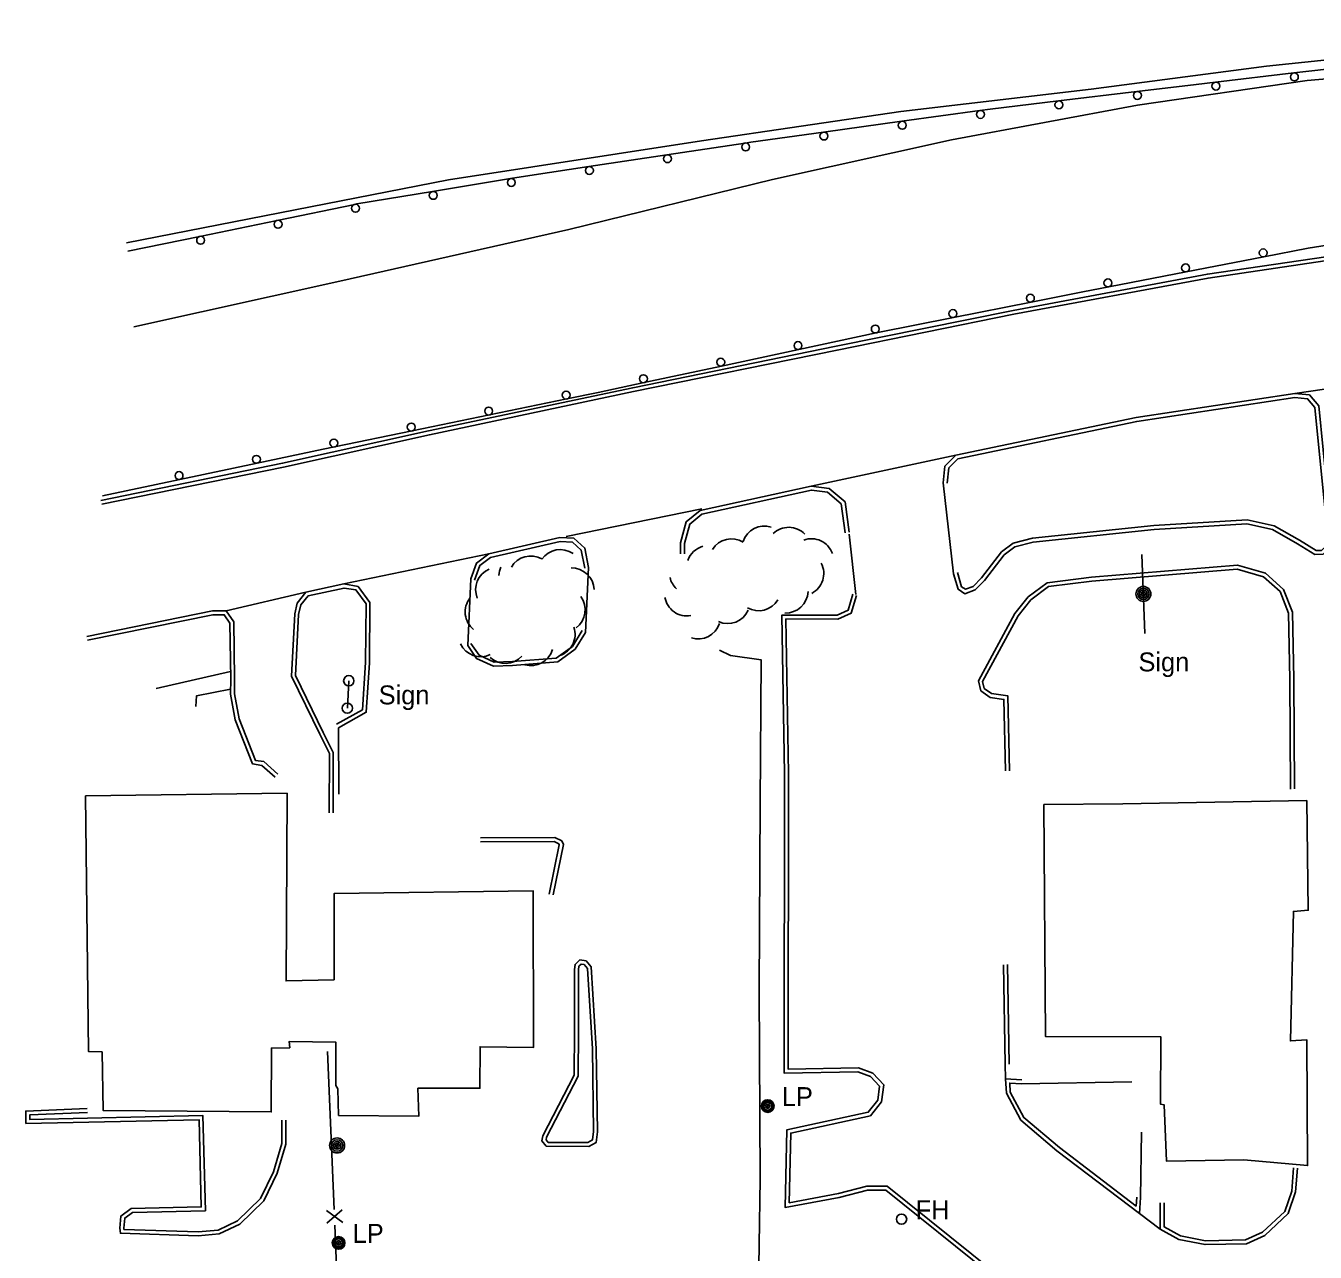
# Model space of a CAD drawing. Extents: x 2402803 to 2427059, y 6985292 to 6997652.
# Drawn here: x 2403480.7 to 2403806.8, y 6991498.2 to 6991808.6 of the extents above; entities that cross this region are included whole.
import ezdxf

# ---------------------------------------------------------------- set-up
doc = ezdxf.new("R2010")
doc.units = 0
for name, color, linetype in [('p_drainage riprap', 7, 'Continuous'), ('p_dtm sidewalk', 7, 'Continuous'), ('p_road - paved curb', 7, 'Continuous'), ('p_road guard rails', 7, 'Continuous'), ('p_structure building', 7, 'Continuous'), ('p_structure fence', 7, 'Continuous'), ('p_structure sign', 7, 'Continuous'), ('p_utility manhole', 7, 'Continuous'), ('p_veg woods', 7, 'Continuous')]:
    doc.layers.add(name, color=color, linetype=linetype)

msp = doc.modelspace()

# ---------------------------------------------------------------- linework, layer by layer
at = {"layer": 'p_drainage riprap'}
msp.add_lwpolyline([(2403508.03, 6991732.43), (2403560.09, 6991744.02), (2403618.02, 6991757.07), (2403669.54, 6991769.69), (2403714.85, 6991779.71), (2403761.84, 6991788.48), (2403804.73, 6991794.78), (2403857.86, 6991799.33), (2403912.85, 6991802.26), (2403942.46, 6991802.6)], dxfattribs=at)
at = {"layer": 'p_dtm sidewalk'}
for points in [[(2403532.49, 6991645.19), (2403513.69, 6991640.88)], [(2403532.5, 6991640.76), (2403523.85, 6991639.01), (2403523.66, 6991636.37)], [(2403732.55, 6991540.86), (2403760.45, 6991541.37)], [(2403762.86, 6991528.63), (2403762.65, 6991512.09)]]:
    msp.add_lwpolyline(points, dxfattribs=at)
at = {"layer": 'p_road - paved curb'}
for points in [[(2403941.62, 6991808.61), (2403890.54, 6991806.45), (2403844.59, 6991803.59), (2403794.47, 6991798.4), (2403750.1, 6991792.54), (2403702.03, 6991786.92), (2403651.62, 6991779.47), (2403587.61, 6991769.62), (2403506.12, 6991753.65)], [(2403499.71, 6991688.52), (2403545.62, 6991697.9), (2403582.56, 6991706.1), (2403634.2, 6991717.03), (2403685.67, 6991727.52), (2403730.43, 6991736.57), (2403779.53, 6991745.76), (2403819.86, 6991751.68), (2403867.19, 6991757.46), (2403897.69, 6991759.96), (2403942.34, 6991762.94)], [(2403499.91, 6991687.54), (2403545.83, 6991696.92), (2403582.77, 6991705.12), (2403634.4, 6991716.05), (2403685.87, 6991726.54), (2403730.62, 6991735.59), (2403779.69, 6991744.77), (2403819.99, 6991750.69), (2403867.29, 6991756.46), (2403897.76, 6991758.96), (2403942.41, 6991761.94)], [(2403801.64, 6991715.52), (2403837.37, 6991720.76)], [(2403715.36, 6991669.96), (2403716.52, 6991666.01), (2403718.2, 6991664.9), (2403720.83, 6991665.83), (2403723.17, 6991668.25), (2403728.16, 6991674.74), (2403730.86, 6991676.76), (2403735.45, 6991677.94), (2403766.03, 6991681.11), (2403789.48, 6991682.61), (2403796.01, 6991681.1), (2403802.32, 6991677.55), (2403806.73, 6991674.79), (2403808.81, 6991674.87), (2403810.81, 6991676.72), (2403811.03, 6991679.01), (2403807.7, 6991712.44), (2403805.34, 6991715.19), (2403801.64, 6991715.52), (2403761.48, 6991709.45), (2403715.93, 6991699.91), (2403713.16, 6991697.17), (2403712.69, 6991692.97)], [(2403716.32, 6991670.24), (2403717.38, 6991666.64), (2403718.34, 6991666.01), (2403720.27, 6991666.69), (2403722.41, 6991668.9), (2403727.45, 6991675.46), (2403730.42, 6991677.68), (2403735.27, 6991678.93), (2403765.95, 6991682.11), (2403789.56, 6991683.62), (2403796.38, 6991682.04), (2403802.83, 6991678.41), (2403807, 6991675.8), (2403808.4, 6991675.86), (2403809.85, 6991677.2), (2403810.03, 6991679.01), (2403806.74, 6991712.03), (2403804.85, 6991714.23), (2403801.67, 6991714.51), (2403761.66, 6991708.47), (2403716.42, 6991698.99), (2403714.11, 6991696.71), (2403713.68, 6991692.86)], [(2403679.34, 6991692.13), (2403715.93, 6991699.91)], [(2403688.89, 6991680.45), (2403687.88, 6991688.13), (2403683.86, 6991691.55), (2403679.34, 6991692.13), (2403651.26, 6991685.92), (2403647.72, 6991683.1), (2403646.25, 6991677.74), (2403646.28, 6991674.95)], [(2403687.9, 6991680.32), (2403686.94, 6991687.62), (2403683.44, 6991690.6), (2403679.39, 6991691.12), (2403651.7, 6991684.99), (2403648.6, 6991682.52), (2403647.25, 6991677.61), (2403647.28, 6991674.96)], [(2403712.69, 6991692.97), (2403715.36, 6991669.96)], [(2403617.39, 6991679.41), (2403651.65, 6991686.36)], [(2403623.04, 6991671.53), (2403622.11, 6991676.45), (2403619.32, 6991678.92), (2403615.72, 6991679.1), (2403597.79, 6991674.99), (2403594.7, 6991672.65), (2403593.21, 6991668.63)], [(2403622.06, 6991671.34), (2403621.19, 6991675.93), (2403618.92, 6991677.94), (2403615.81, 6991678.09), (2403598.22, 6991674.06), (2403595.54, 6991672.03), (2403594.15, 6991668.28)], [(2403690.64, 6991664.68), (2403688.89, 6991679.92)], [(2403561.16, 6991667.37), (2403597.79, 6991674.99)], [(2403622.24, 6991655.06), (2403623.04, 6991671.53)], [(2403801.53, 6991615.48), (2403801.37, 6991643.25), (2403801.05, 6991660.19), (2403798.76, 6991665.99), (2403794.22, 6991670.1), (2403787.13, 6991672.11), (2403750.24, 6991669.04), (2403738.98, 6991667.66), (2403734.2, 6991664.07), (2403730.8, 6991659.87), (2403721.6, 6991642.83), (2403722.19, 6991640.34), (2403724.57, 6991638.66), (2403728.09, 6991638.16), (2403728.45, 6991620.05)], [(2403593.21, 6991668.63), (2403592.45, 6991651.77)], [(2403800.53, 6991615.47), (2403800.37, 6991643.24), (2403800.05, 6991659.99), (2403797.92, 6991665.41), (2403793.72, 6991669.2), (2403787.03, 6991671.1), (2403750.34, 6991668.05), (2403739.37, 6991666.7), (2403734.9, 6991663.34), (2403731.64, 6991659.31), (2403722.66, 6991642.69), (2403723.08, 6991640.94), (2403724.95, 6991639.62), (2403729.07, 6991639.03), (2403729.45, 6991620.07)], [(2403531.4, 6991660.55), (2403551.55, 6991665.24)], [(2403559.78, 6991630.98), (2403566.79, 6991634.9), (2403567.6, 6991647.44), (2403567.74, 6991662.68), (2403564.73, 6991666.75), (2403561.16, 6991667.35), (2403551.55, 6991665.24), (2403549.29, 6991662.5), (2403548.7, 6991659.79), (2403547.89, 6991643.99), (2403555.03, 6991629.36), (2403557.47, 6991624.47), (2403557.4, 6991609.41)], [(2403559.29, 6991631.85), (2403565.83, 6991635.51), (2403566.6, 6991647.48), (2403566.74, 6991662.35), (2403564.17, 6991665.83), (2403561.19, 6991666.33), (2403552.1, 6991664.34), (2403550.22, 6991662.05), (2403549.69, 6991659.66), (2403548.9, 6991644.2), (2403555.93, 6991629.8), (2403558.47, 6991624.7), (2403558.4, 6991609.41)], [(2403745.15, 6991461.32), (2403733.78, 6991484.34), (2403730.03, 6991488.75), (2403724.46, 6991492.84), (2403698.18, 6991513.95), (2403693.56, 6991513.93), (2403686.42, 6991512.13), (2403672.73, 6991509.57), (2403673.17, 6991529.23), (2403693.76, 6991533.69), (2403696.18, 6991536.72), (2403696.64, 6991540.25), (2403694.35, 6991542.71), (2403691.12, 6991543.89), (2403672.49, 6991543.59), (2403672.57, 6991619.4), (2403671.91, 6991659.5), (2403685.88, 6991659.47), (2403688.64, 6991660.72), (2403689.84, 6991664.75)], [(2403746.05, 6991461.76), (2403734.62, 6991484.89), (2403730.72, 6991489.49), (2403725.07, 6991493.63), (2403698.53, 6991514.95), (2403693.43, 6991514.93), (2403686.21, 6991513.11), (2403673.76, 6991510.78), (2403674.15, 6991528.42), (2403694.32, 6991532.79), (2403697.14, 6991536.31), (2403697.69, 6991540.59), (2403694.92, 6991543.57), (2403691.29, 6991544.89), (2403673.49, 6991544.61), (2403673.57, 6991619.41), (2403672.93, 6991658.5), (2403686.1, 6991658.47), (2403689.47, 6991660), (2403690.8, 6991664.46)], [(2403544.46, 6991619.21), (2403540.87, 6991622.39), (2403538.76, 6991622.72), (2403534.62, 6991633.21), (2403533.49, 6991639.53), (2403533.51, 6991643.39), (2403533.32, 6991657.75), (2403531.4, 6991660.55), (2403527.87, 6991660.54), (2403496.12, 6991654.09)], [(2403543.8, 6991618.46), (2403540.43, 6991621.45), (2403538.04, 6991621.82), (2403533.65, 6991632.94), (2403532.49, 6991639.44), (2403532.51, 6991643.39), (2403532.32, 6991657.43), (2403530.87, 6991659.55), (2403527.97, 6991659.54), (2403496.32, 6991653.11)], [(2403592.45, 6991651.77), (2403594.66, 6991648.52), (2403598.94, 6991646.57), (2403603.81, 6991646.72), (2403615.21, 6991647.65), (2403619.67, 6991650.86), (2403622.24, 6991655.06)], [(2403593.28, 6991652.33), (2403595.33, 6991649.31), (2403599.14, 6991647.58), (2403603.75, 6991647.72), (2403614.85, 6991648.62), (2403618.92, 6991651.55), (2403621.39, 6991655.58)], [(2403674.78, 6991469.39), (2403674.72, 6991483.7), (2403665.92, 6991483.64), (2403666.4, 6991516.73), (2403666.15, 6991564.58), (2403666.42, 6991611.88), (2403666.66, 6991648.16), (2403658.88, 6991649.28), (2403656.13, 6991650.61)], [(2403559.86, 6991614.17), (2403559.78, 6991630.98)], [(2403614.07, 6991588.69), (2403616.65, 6991601.42), (2403616.24, 6991602.37), (2403614.52, 6991603.2), (2403595.73, 6991603.12)], [(2403613.09, 6991588.89), (2403615.61, 6991601.31), (2403615.47, 6991601.63), (2403614.29, 6991602.2), (2403595.73, 6991602.12)], [(2403624.98, 6991549.76), (2403623.7, 6991570.46), (2403622.41, 6991572.01), (2403620.78, 6991572.23), (2403619.6, 6991571.08), (2403619.48, 6991569.78), (2403619.49, 6991554.2)], [(2403623.98, 6991549.7), (2403622.72, 6991570.07), (2403621.89, 6991571.07), (2403621.13, 6991571.17), (2403620.56, 6991570.62), (2403620.48, 6991569.73), (2403620.49, 6991554.2)], [(2403727.96, 6991571), (2403728.36, 6991545.84)], [(2403728.96, 6991571.02), (2403729.36, 6991545.86)], [(2403619.49, 6991554.2), (2403619.38, 6991543.05), (2403611.44, 6991527.7), (2403611.18, 6991526.44), (2403612.34, 6991525.05), (2403623.1, 6991525.04), (2403624.93, 6991526.01), (2403625.29, 6991528.71), (2403624.98, 6991549.76)], [(2403620.49, 6991554.19), (2403620.38, 6991542.8), (2403612.39, 6991527.36), (2403612.26, 6991526.71), (2403612.81, 6991526.05), (2403622.85, 6991526.04), (2403624.01, 6991526.65), (2403624.29, 6991528.77), (2403623.98, 6991549.75)], [(2403728.36, 6991545.84), (2403728.47, 6991542.14)], [(2403732.62, 6991541.86), (2403728.47, 6991542.14), (2403728.69, 6991538.47), (2403732.35, 6991531.7), (2403741.49, 6991523.94), (2403762.34, 6991508.02), (2403762.65, 6991512.09)], [(2403732.55, 6991540.86), (2403729.54, 6991541.07), (2403729.67, 6991538.75), (2403733.14, 6991532.34), (2403742.12, 6991524.72), (2403761.48, 6991509.93), (2403761.65, 6991512.17)], [(2403496.22, 6991534.58), (2403480.69, 6991533.95), (2403480.72, 6991530.84), (2403524.51, 6991531.79), (2403525.07, 6991509.71), (2403507.3, 6991509.3), (2403504.76, 6991507.41), (2403504.47, 6991504.32), (2403504.64, 6991503.07), (2403524.31, 6991502.38), (2403529.6, 6991502.89), (2403534.8, 6991505.33), (2403540.86, 6991511.24), (2403544.28, 6991518.27), (2403546.42, 6991525.61), (2403546.47, 6991531.68)], [(2403496.26, 6991533.58), (2403481.7, 6991532.99), (2403481.71, 6991531.86), (2403525.48, 6991532.81), (2403526.1, 6991508.73), (2403507.64, 6991508.31), (2403505.71, 6991506.87), (2403505.48, 6991504.34), (2403505.52, 6991504.04), (2403524.28, 6991503.38), (2403529.33, 6991503.87), (2403534.22, 6991506.16), (2403540.04, 6991511.83), (2403543.34, 6991518.63), (2403545.42, 6991525.76), (2403545.47, 6991531.69)], [(2403767.58, 6991510.76), (2403767.62, 6991504.08), (2403772.35, 6991501.49), (2403778.96, 6991500.17), (2403789.41, 6991500.35), (2403794.07, 6991502.45), (2403799.95, 6991508.01), (2403801.84, 6991513.53), (2403802.29, 6991519.5)], [(2403768.58, 6991510.77), (2403768.62, 6991504.67), (2403772.7, 6991502.44), (2403779.05, 6991501.17), (2403789.19, 6991501.35), (2403793.51, 6991503.29), (2403799.08, 6991508.57), (2403800.85, 6991513.73), (2403801.29, 6991519.58)], [(2403762.34, 6991508.02), (2403767.62, 6991504.08)]]:
    msp.add_lwpolyline(points, dxfattribs=at)
at = {"layer": 'p_road guard rails'}
for p, q in [((2403821.27, 6991799), (2403801.42, 6991796.67)), ((2403801.42, 6991796.67), (2403781.56, 6991794.33)), ((2403761.71, 6991791.97), (2403741.86, 6991789.59)), ((2403722.01, 6991787.17), (2403702.21, 6991784.43)), ((2403702.21, 6991784.43), (2403682.41, 6991781.7)), ((2403662.61, 6991778.94), (2403642.85, 6991775.96)), ((2403642.85, 6991775.96), (2403623.08, 6991772.97)), ((2403603.32, 6991769.93), (2403583.59, 6991766.68)), ((2403563.87, 6991763.41), (2403544.29, 6991759.36)), ((2403544.29, 6991759.36), (2403524.71, 6991755.31)), ((2403524.71, 6991755.31), (2403506.53, 6991751.55)), ((2403774.2, 6991746.36), (2403793.83, 6991750.17)), ((2403754.57, 6991742.55), (2403774.2, 6991746.36)), ((2403715.35, 6991734.8), (2403734.96, 6991738.69)), ((2403676.2, 6991726.7), (2403695.75, 6991730.9)), ((2403656.66, 6991722.51), (2403676.2, 6991726.7)), ((2403637.11, 6991718.31), (2403656.66, 6991722.51)), ((2403597.97, 6991710.13), (2403617.55, 6991714.18)), ((2403578.38, 6991706.08), (2403597.97, 6991710.13)), ((2403558.8, 6991702.03), (2403578.38, 6991706.08)), ((2403519.66, 6991693.81), (2403539.23, 6991697.93)), ((2403500.09, 6991689.7), (2403519.66, 6991693.81))]:
    msp.add_line(p, q, dxfattribs=at)
for points in [[(2403781.56, 6991794.33), (2403776.67, 6991793.76), (2403761.71, 6991791.97)], [(2403741.86, 6991789.59), (2403724.61, 6991787.53), (2403722.01, 6991787.17)], [(2403682.41, 6991781.7), (2403664.04, 6991779.16), (2403662.61, 6991778.94)], [(2403623.08, 6991772.97), (2403608.15, 6991770.72), (2403603.32, 6991769.93)], [(2403583.59, 6991766.68), (2403564.42, 6991763.52), (2403563.87, 6991763.41)], [(2403793.83, 6991750.17), (2403805.05, 6991752.34), (2403813.5, 6991753.69)], [(2403734.96, 6991738.69), (2403748, 6991741.28), (2403754.57, 6991742.55)], [(2403695.75, 6991730.9), (2403696.14, 6991730.98), (2403715.35, 6991734.8)], [(2403617.55, 6991714.18), (2403625.44, 6991715.81), (2403637.11, 6991718.31)], [(2403539.23, 6991697.93), (2403555.9, 6991701.43), (2403558.8, 6991702.03)]]:
    msp.add_lwpolyline(points, dxfattribs=at)
for centre in [(2403801.53, 6991795.67), (2403761.83, 6991790.98), (2403781.68, 6991793.34), (2403741.98, 6991788.6), (2403722.15, 6991786.18), (2403702.35, 6991783.44), (2403662.76, 6991777.96), (2403682.55, 6991780.71), (2403642.99, 6991774.97), (2403623.23, 6991771.99), (2403603.49, 6991768.94), (2403583.75, 6991765.69), (2403564.07, 6991762.43), (2403544.49, 6991758.38), (2403524.91, 6991754.33), (2403793.64, 6991751.15), (2403774.01, 6991747.34), (2403754.38, 6991743.54), (2403734.76, 6991739.67), (2403715.16, 6991735.78), (2403695.54, 6991731.87), (2403675.99, 6991727.68), (2403656.45, 6991723.49), (2403636.9, 6991719.29), (2403617.35, 6991715.16), (2403597.76, 6991711.11), (2403578.18, 6991707.06), (2403558.6, 6991703.01), (2403539.02, 6991698.9), (2403519.45, 6991694.79)]:
    msp.add_circle(centre, 1, dxfattribs=at)
at = {"layer": 'p_structure building'}
msp.add_lwpolyline([(2403495.8, 6991613.73), (2403496.55, 6991549.06), (2403500, 6991548.96), (2403500.3, 6991534.08), (2403542.76, 6991533.75), (2403542.82, 6991549.9), (2403547.43, 6991550), (2403547.34, 6991551.59), (2403559.14, 6991551.38), (2403559.14, 6991540.48), (2403559.6, 6991539.58), (2403559.82, 6991532.88), (2403580.08, 6991532.65), (2403579.88, 6991539.75), (2403595.53, 6991539.74), (2403595.59, 6991550.24), (2403609.09, 6991550.03), (2403609.03, 6991589.7), (2403558.7, 6991589.06), (2403558.67, 6991567.21), (2403546.53, 6991566.91), (2403546.76, 6991614.38)], close=True, dxfattribs=at)
for points in [[(2403738.13, 6991611.57), (2403738.56, 6991552.86), (2403767.73, 6991552.79), (2403767.63, 6991535.74), (2403768.56, 6991535.59), (2403769.23, 6991521.28), (2403788.77, 6991521.67), (2403804.88, 6991520.16), (2403804.68, 6991552.01), (2403800.55, 6991551.73), (2403801.29, 6991584.49), (2403805.06, 6991584.79), (2403804.66, 6991612.52), (2403758.12, 6991611.73)], [(2403758.12, 6991611.73), (2403738.13, 6991611.57)]]:
    msp.add_lwpolyline(points, dxfattribs=at)
at = {"layer": 'p_structure fence'}
for p, q in [((2403557, 6991549.05), (2403558.67, 6991509.08)), ((2403556.71, 6991508.8), (2403560.84, 6991505.77)), ((2403556.84, 6991505.61), (2403560.71, 6991508.97))]:
    msp.add_line(p, q, dxfattribs=at)
msp.add_lwpolyline([(2403558.84, 6991505.09), (2403559.89, 6991479.89), (2403571.2, 6991479.79), (2403571.22, 6991476.33)], dxfattribs=at)
at = {"layer": 'p_structure sign'}
for p, q in [((2403763.75, 6991654.84), (2403762.93, 6991674.82)), ((2403562.02, 6991635.91), (2403562.38, 6991642.86))]:
    msp.add_line(p, q, dxfattribs=at)
for centre, radius in [((2403763.34, 6991664.83), 1.9), ((2403763.34, 6991664.83), 1.44), ((2403763.34, 6991664.83), 0.973), ((2403763.34, 6991664.83), 0.539), ((2403763.34, 6991664.83), 0.192), ((2403562.37, 6991642.87), 1.3), ((2403562.01, 6991635.92), 1.3)]:
    msp.add_circle(centre, radius, dxfattribs=at)
at = {"layer": 'p_utility manhole'}
for centre, radius in [((2403668.34, 6991535.22), 1.6), ((2403668.34, 6991535.22), 1.3), ((2403668.34, 6991535.22), 1), ((2403668.34, 6991535.22), 0.539), ((2403668.34, 6991535.22), 0.192), ((2403559.43, 6991525.27), 1.9), ((2403559.43, 6991525.27), 1.44), ((2403559.43, 6991525.27), 0.973), ((2403559.43, 6991525.27), 0.539), ((2403559.43, 6991525.27), 0.192), ((2403702.19, 6991506.61), 1.3), ((2403559.8, 6991500.61), 1.6), ((2403559.8, 6991500.61), 1.3), ((2403559.8, 6991500.61), 1), ((2403559.8, 6991500.61), 0.539), ((2403559.8, 6991500.61), 0.192)]:
    msp.add_circle(centre, radius, dxfattribs=at)
at = {"layer": 'p_veg woods'}
for centre, start, end in [((2403667.5, 6991676.38), 72.4916, 162.4916), ((2403673.63, 6991676.04), 44.0791, 134.0791), ((2403659.16, 6991673.12), 58.09, 148.09), ((2403679.38, 6991673.16), 19.8259, 109.8259), ((2403615.87, 6991670.4), 55.2775, 145.2775), ((2403653.45, 6991671.44), 105.2861, 160.6302), ((2403606, 6991669.38), 156.3698, 178.6678), ((2403608.41, 6991668.79), 60.3981, 150.3981), ((2403618.76, 6991665.77), 1.6468, 91.6468), ((2403676.86, 6991670), 297.2949, 27.2949), ((2403600.1, 6991665.91), 112.6833, 202.6833), ((2403649.14, 6991670.23), 192.7705, 226.2415), ((2403672.88, 6991665.65), 267.8425, 357.8425), ((2403597.46, 6991660.29), 141.6919, 231.6919), ((2403616.52, 6991660.77), 307.026, 37.026), ((2403647.9, 6991664.92), 189.8159, 279.8159), ((2403666.04, 6991666.23), 239.5868, 329.5868), ((2403658.22, 6991662.98), 246.0472, 336.0472), ((2403613.97, 6991654.61), 288.3171, 18.3171), ((2403650.75, 6991659.08), 252.1221, 342.1221), ((2403595.76, 6991654.59), 205.3151, 295.3151), ((2403602.01, 6991652.91), 226.9805, 316.9805), ((2403608.44, 6991652.33), 253.9675, 343.9675)]:
    msp.add_arc(centre, 5.65, start, end, dxfattribs=at)

# ---------------------------------------------------------------- texts
at = {"layer": 'p_structure sign'}
for p in [(2403762.1, 6991645.23), (2403569.94, 6991636.88)]:
    msp.add_text('Sign', height=4.8, dxfattribs=at).set_placement(p)
at = {"layer": 'p_utility manhole'}
for s, p in [('  LP', (2403668.34, 6991535.22)), ('  FH', (2403702.18, 6991506.6)), ('  LP', (2403559.8, 6991500.61))]:
    msp.add_text(s, height=4.8, dxfattribs=at).set_placement(p)

doc.saveas('drawing.dxf')
